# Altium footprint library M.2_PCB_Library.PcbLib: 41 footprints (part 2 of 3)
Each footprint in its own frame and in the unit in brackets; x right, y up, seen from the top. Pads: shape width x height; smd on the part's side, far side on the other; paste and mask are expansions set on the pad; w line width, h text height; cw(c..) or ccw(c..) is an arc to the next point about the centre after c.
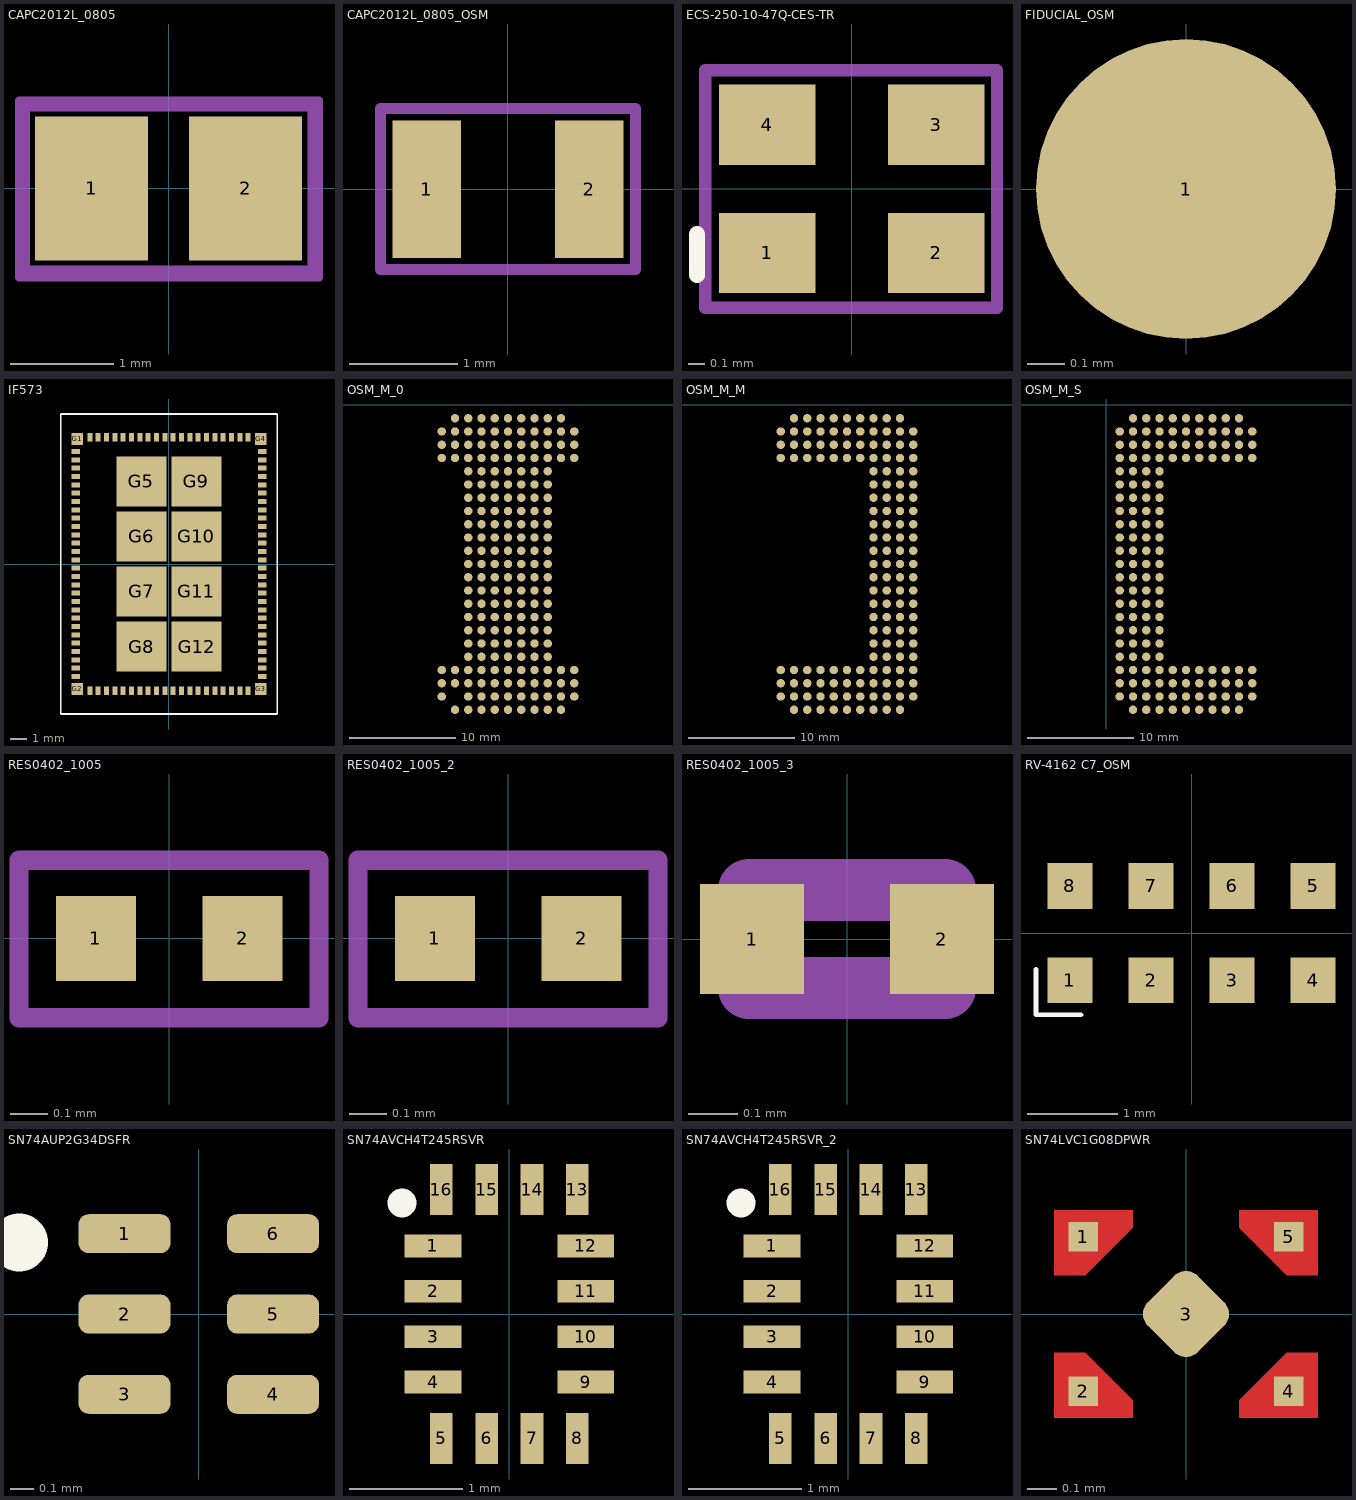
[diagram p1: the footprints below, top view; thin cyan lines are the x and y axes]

## CAPC2012L_0805 [mm] "Chip Capacitor, Body 2.0x1.3mm, IPC High Density"
height 1.1
pads (2):
  rect 1.1x1.4 smd paste-0.12 mask+0.06: 1(-0.75,0) 2(0.75,0)
Mechanical 9:
  lines w0.076: -1.455,-0.866 1.463,-0.866 1.463,0.853 -1.455,0.853 -1.455,-0.866
Top Assembly:
  lines w0.102: -1.4,-0.8 -1.4,0.8 1.4,0.8 1.4,-0.8 -1.4,-0.8
  text "'.Designator'" at -1.311,-0.305 h1.02
3D body "CAP0805.stp": height 0.78, standoff 0, extent -1,-0.625 1,0.625

## CAPC2012L_0805_OSM [mm] "Chip Capacitor, Body 2.0x1.3mm, IPC High Density"
height 1.1
pads (2):
  rect 0.635x1.27 smd paste-0.12 mask+0.06: 1(-0.75,0) 2(0.75,0)
Mechanical 9:
  lines w0.076: -1.165,-0.732 -1.165,0.733 1.166,0.733 1.166,-0.732 -1.165,-0.732
Top Assembly:
  lines w0.102: -1.178,-0.745 1.179,-0.745 1.179,0.746 -1.178,0.746 -1.178,-0.745
  text "'.Designator'" at -1.965,-0.277 h1.02
3D body "CAP0805.stp": height 0.78, standoff 0, extent -1,-0.625 1,0.625

## ECS-250-10-47Q-CES-TR [mm]
height 0.6
pads (4):
  rect 0.6x0.5 smd paste-0.08 mask+0.06: 1(-0.525,-0.398) 2(0.525,-0.398) 3(0.525,0.398) 4(-0.525,0.398)
Top Overlay:
  lines w0.102: -0.962,-0.535 -0.962,-0.281
Mechanical 9:
  lines w0.076: -0.911,-0.738 -0.911,0.737 0.903,0.737 0.903,-0.738 -0.911,-0.738
Top Assembly:
  text "'.Designator'" at -1.717,-0.155 h0.76
3D body "ECS-250-10-47Q-CES-TR.stp": height 0.45, standoff 0, extent -0.835,-0.635 0.835,0.635

## FIDUCIAL_OSM [mm]
pads (1):
  round 0.8 smd paste+0 mask+0: 1(0,0)
Mechanical 1:

## IF573 [mm] "BD1249, 0ZCA0110FF2E,"
height 0.8
pads (108):
  rect 0.5x0.3 smd mask+0.051: 1(-5.594,6.76) 2(-5.594,6.26) 3(-5.594,5.76) 4(-5.594,5.26) 5(-5.594,4.76) 6(-5.594,4.26) 7(-5.594,3.76) 8(-5.594,3.26) 9(-5.594,2.76) 10(-5.594,2.26) 11(-5.594,1.76) 12(-5.594,1.26) 13(-5.594,0.76) 14(-5.594,0.26) 15(-5.594,-0.24) 16(-5.594,-0.74) 17(-5.594,-1.24) 18(-5.594,-1.74) 19(-5.594,-2.24) 20(-5.594,-2.74) 21(-5.594,-3.24) 22(-5.594,-3.74) 23(-5.594,-4.24) 24(-5.594,-4.74) 25(-5.594,-5.24) 26(-5.594,-5.74) 27(-5.594,-6.24) 28(-5.594,-6.74) 49(5.606,-6.74) 50(5.606,-6.24) 51(5.606,-5.74) 52(5.606,-5.24) 53(5.606,-4.74) 54(5.606,-4.24) 55(5.606,-3.74) 56(5.606,-3.24) 57(5.606,-2.74) 58(5.606,-2.24) 59(5.606,-1.74) 60(5.606,-1.24) 61(5.606,-0.74) 62(5.606,-0.24) 63(5.606,0.26) 64(5.606,0.76) 65(5.606,1.26) 66(5.606,1.76) 67(5.606,2.26) 68(5.606,2.76) 69(5.606,3.26) 70(5.606,3.76) 71(5.606,4.26) 72(5.606,4.76) 73(5.606,5.26) 74(5.606,5.76) 75(5.606,6.26) 76(5.606,6.76)
  rect 0.3x0.5 smd mask+0.051: 29(-4.744,-7.59) 30(-4.244,-7.59) 31(-3.744,-7.59) 32(-3.244,-7.59) 33(-2.744,-7.59) 34(-2.244,-7.59) 35(-1.744,-7.59) 36(-1.244,-7.59) 37(-0.744,-7.59) 38(-0.244,-7.59) 39(0.256,-7.59) 40(0.756,-7.59) 41(1.256,-7.59) 42(1.756,-7.59) 43(2.256,-7.59) 44(2.756,-7.59) 45(3.256,-7.59) 46(3.756,-7.59) 47(4.256,-7.59) 48(4.756,-7.59) 77(4.756,7.61) 78(4.256,7.61) 79(3.756,7.61) 80(3.256,7.61) 81(2.756,7.61) 82(2.256,7.61) 83(1.756,7.61) 84(1.256,7.61) 85(0.756,7.61) 86(0.256,7.61) 87(-0.244,7.61) 88(-0.744,7.61) 89(-1.244,7.61) 90(-1.744,7.61) 91(-2.244,7.61) 92(-2.744,7.61) 93(-3.244,7.61) 94(-3.744,7.61) 95(-4.244,7.61) 96(-4.744,7.61)
  rect 0.7x0.7 smd mask+0.051: G1(-5.494,7.51) G2(-5.494,-7.49) G3(5.506,-7.49) G4(5.506,7.51)
  rect 3x3 smd mask+0.051: G5(-1.644,4.96) G6(-1.644,1.66) G7(-1.644,-1.64) G8(-1.644,-4.94) G9(1.656,4.96) G10(1.656,1.66) G11(1.656,-1.64) G12(1.656,-4.94)
Top Overlay:
  lines w0.102: -6.494,-8.99 -6.494,9.01 6.506,9.01 6.506,-8.99 -6.494,-8.99
3D body "453-00117-R1.0.STEP": height 1.94, standoff 0.01, extent -6.494,-8.99 6.506,9.01

## OSM_M_0 [mm]
height 1.5
pads (188):
  round 0.8 smd: A14(17.5,-28.75) A15(18.75,-28.75) A16(20,-28.75) A17(21.25,-28.75) A18(22.5,-28.75) A19(23.75,-28.75) A20(25,-28.75) A21(26.25,-28.75) A22(27.5,-28.75) AA13(16.25,-3.75) AA14(17.5,-3.75) AA15(18.75,-3.75) AA16(20,-3.75) AA17(21.25,-3.75) AA18(22.5,-3.75) AA19(23.75,-3.75) AA20(25,-3.75) AA21(26.25,-3.75) AA22(27.5,-3.75) AA23(28.75,-3.75) AB13(16.25,-2.5) AB14(17.5,-2.5) AB15(18.75,-2.5) AB16(20,-2.5) AB17(21.25,-2.5) AB18(22.5,-2.5) AB19(23.75,-2.5) AB20(25,-2.5) AB21(26.25,-2.5) AB22(27.5,-2.5) AB23(28.75,-2.5) AC14(17.5,-1.25) AC15(18.75,-1.25) AC16(20,-1.25) AC17(21.25,-1.25) AC18(22.5,-1.25) AC19(23.75,-1.25) AC20(25,-1.25) AC21(26.25,-1.25) AC22(27.5,-1.25) B13(16.25,-27.5) B15(18.75,-27.5) B16(20,-27.5) B17(21.25,-27.5) B18(22.5,-27.5) B19(23.75,-27.5) B20(25,-27.5) B21(26.25,-27.5) B22(27.5,-27.5) B23(28.75,-27.5) C13(16.25,-26.25) C14(17.5,-26.25) C15(18.75,-26.25) C16(20,-26.25) C17(21.25,-26.25) C18(22.5,-26.25) C19(23.75,-26.25) C20(25,-26.25) C21(26.25,-26.25) C22(27.5,-26.25) C23(28.75,-26.25) D13(16.25,-25) D14(17.5,-25) D15(18.75,-25) D16(20,-25) D17(21.25,-25) D18(22.5,-25) D19(23.75,-25) D20(25,-25) D21(26.25,-25) D22(27.5,-25) D23(28.75,-25) E15(18.75,-23.75) E16(20,-23.75) E17(21.25,-23.75) E18(22.5,-23.75) E19(23.75,-23.75) E20(25,-23.75) E21(26.25,-23.75) F15(18.75,-22.5) F16(20,-22.5) F17(21.25,-22.5) F18(22.5,-22.5) F19(23.75,-22.5) F20(25,-22.5) F21(26.25,-22.5) G15(18.75,-21.25) G16(20,-21.25) G17(21.25,-21.25) G18(22.5,-21.25) G19(23.75,-21.25) G20(25,-21.25) G21(26.25,-21.25) H15(18.75,-20) H16(20,-20) H17(21.25,-20) H18(22.5,-20) H19(23.75,-20) H20(25,-20) H21(26.25,-20) J15(18.75,-18.75) J16(20,-18.75) J17(21.25,-18.75) J18(22.5,-18.75) J19(23.75,-18.75) J20(25,-18.75) J21(26.25,-18.75) K15(18.75,-17.5) K16(20,-17.5) K17(21.25,-17.5) K18(22.5,-17.5) K19(23.75,-17.5) K20(25,-17.5) K21(26.25,-17.5) L15(18.75,-16.25) L16(20,-16.25) L17(21.25,-16.25) L18(22.5,-16.25) L19(23.75,-16.25) L20(25,-16.25) L21(26.25,-16.25) M15(18.75,-15) M16(20,-15) M17(21.25,-15) M18(22.5,-15) M19(23.75,-15) M20(25,-15) M21(26.25,-15) N15(18.75,-13.75) N16(20,-13.75) N17(21.25,-13.75) N18(22.5,-13.75) N19(23.75,-13.75) N20(25,-13.75) N21(26.25,-13.75) P15(18.75,-12.5) P16(20,-12.5) P17(21.25,-12.5) P18(22.5,-12.5) P19(23.75,-12.5) P20(25,-12.5) P21(26.25,-12.5) R15(18.75,-11.25) R16(20,-11.25) R17(21.25,-11.25) R18(22.5,-11.25) R19(23.75,-11.25) R20(25,-11.25) R21(26.25,-11.25) T15(18.75,-10) T16(20,-10) T17(21.25,-10) T18(22.5,-10) T19(23.75,-10) T20(25,-10) T21(26.25,-10) U15(18.75,-8.75) U16(20,-8.75) U17(21.25,-8.75) U18(22.5,-8.75) U19(23.75,-8.75) U20(25,-8.75) U21(26.25,-8.75) V15(18.75,-7.5) V16(20,-7.5) V17(21.25,-7.5) V18(22.5,-7.5) V19(23.75,-7.5) V20(25,-7.5) V21(26.25,-7.5) W15(18.75,-6.25) W16(20,-6.25) W17(21.25,-6.25) W18(22.5,-6.25) W19(23.75,-6.25) W20(25,-6.25) W21(26.25,-6.25) Y13(16.25,-5) Y14(17.5,-5) Y15(18.75,-5) Y16(20,-5) Y17(21.25,-5) Y18(22.5,-5) Y19(23.75,-5) Y20(25,-5) Y21(26.25,-5) Y22(27.5,-5) Y23(28.75,-5)

## OSM_M_M [mm]
height 1.5
pads (144):
  round 0.8 smd: A26(32.5,-28.75) A27(33.75,-28.75) A28(35,-28.75) A29(36.25,-28.75) A30(37.5,-28.75) A31(38.75,-28.75) A32(40,-28.75) A33(41.25,-28.75) A34(42.5,-28.75) AA25(31.25,-3.75) AA26(32.5,-3.75) AA27(33.75,-3.75) AA28(35,-3.75) AA29(36.25,-3.75) AA30(37.5,-3.75) AA31(38.75,-3.75) AA32(40,-3.75) AA33(41.25,-3.75) AA34(42.5,-3.75) AA35(43.75,-3.75) AB25(31.25,-2.5) AB26(32.5,-2.5) AB27(33.75,-2.5) AB28(35,-2.5) AB29(36.25,-2.5) AB30(37.5,-2.5) AB31(38.75,-2.5) AB32(40,-2.5) AB33(41.25,-2.5) AB34(42.5,-2.5) AB35(43.75,-2.5) AC26(32.5,-1.25) AC27(33.75,-1.25) AC28(35,-1.25) AC29(36.25,-1.25) AC30(37.5,-1.25) AC31(38.75,-1.25) AC32(40,-1.25) AC33(41.25,-1.25) AC34(42.5,-1.25) B25(31.25,-27.5) B26(32.5,-27.5) B27(33.75,-27.5) B28(35,-27.5) B29(36.25,-27.5) B30(37.5,-27.5) B31(38.75,-27.5) B32(40,-27.5) B33(41.25,-27.5) B34(42.5,-27.5) B35(43.75,-27.5) C25(31.25,-26.25) C26(32.5,-26.25) C27(33.75,-26.25) C28(35,-26.25) C29(36.25,-26.25) C30(37.5,-26.25) C31(38.75,-26.25) C32(40,-26.25) C33(41.25,-26.25) C34(42.5,-26.25) C35(43.75,-26.25) D25(31.25,-25) D26(32.5,-25) D27(33.75,-25) D28(35,-25) D29(36.25,-25) D30(37.5,-25) D31(38.75,-25) D32(40,-25) D33(41.25,-25) D34(42.5,-25) D35(43.75,-25) E32(40,-23.75) E33(41.25,-23.75) E34(42.5,-23.75) E35(43.75,-23.75) F32(40,-22.5) F33(41.25,-22.5) F34(42.5,-22.5) F35(43.75,-22.5) G32(40,-21.25) G33(41.25,-21.25) G34(42.5,-21.25) G35(43.75,-21.25) H32(40,-20) H33(41.25,-20) H34(42.5,-20) H35(43.75,-20) J32(40,-18.75) J33(41.25,-18.75) J34(42.5,-18.75) J35(43.75,-18.75) K32(40,-17.5) K33(41.25,-17.5) K34(42.5,-17.5) K35(43.75,-17.5) L32(40,-16.25) L33(41.25,-16.25) L34(42.5,-16.25) L35(43.75,-16.25) M32(40,-15) M33(41.25,-15) M34(42.5,-15) M35(43.75,-15) N32(40,-13.75) N33(41.25,-13.75) N34(42.5,-13.75) N35(43.75,-13.75) P32(40,-12.5) P33(41.25,-12.5) P34(42.5,-12.5) P35(43.75,-12.5) R32(40,-11.25) R33(41.25,-11.25) R34(42.5,-11.25) R35(43.75,-11.25) T32(40,-10) T33(41.25,-10) T34(42.5,-10) T35(43.75,-10) U32(40,-8.75) U33(41.25,-8.75) U34(42.5,-8.75) U35(43.75,-8.75) V32(40,-7.5) V33(41.25,-7.5) V34(42.5,-7.5) V35(43.75,-7.5) W32(40,-6.25) W33(41.25,-6.25) W34(42.5,-6.25) W35(43.75,-6.25) Y25(31.25,-5) Y26(32.5,-5) Y27(33.75,-5) Y28(35,-5) Y29(36.25,-5) Y30(37.5,-5) Y31(38.75,-5) Y32(40,-5) Y33(41.25,-5) Y34(42.5,-5) Y35(43.75,-5)

## OSM_M_S [mm]
height 1.5
pads (144):
  round 0.8 smd: A2(2.5,-28.75) A3(3.75,-28.75) A4(5,-28.75) A5(6.25,-28.75) A6(7.5,-28.75) A7(8.75,-28.75) A8(10,-28.75) A9(11.25,-28.75) A10(12.5,-28.75) AA1(1.25,-3.75) AA2(2.5,-3.75) AA3(3.75,-3.75) AA4(5,-3.75) AA5(6.25,-3.75) AA6(7.5,-3.75) AA7(8.75,-3.75) AA8(10,-3.75) AA9(11.25,-3.75) AA10(12.5,-3.75) AA11(13.75,-3.75) AB1(1.25,-2.5) AB2(2.5,-2.5) AB3(3.75,-2.5) AB4(5,-2.5) AB5(6.25,-2.5) AB6(7.5,-2.5) AB7(8.75,-2.5) AB8(10,-2.5) AB9(11.25,-2.5) AB10(12.5,-2.5) AB11(13.75,-2.5) AC2(2.5,-1.25) AC3(3.75,-1.25) AC4(5,-1.25) AC5(6.25,-1.25) AC6(7.5,-1.25) AC7(8.75,-1.25) AC8(10,-1.25) AC9(11.25,-1.25) AC10(12.5,-1.25) B1(1.25,-27.5) B2(2.5,-27.5) B3(3.75,-27.5) B4(5,-27.5) B5(6.25,-27.5) B6(7.5,-27.5) B7(8.75,-27.5) B8(10,-27.5) B9(11.25,-27.5) B10(12.5,-27.5) B11(13.75,-27.5) C1(1.25,-26.25) C2(2.5,-26.25) C3(3.75,-26.25) C4(5,-26.25) C5(6.25,-26.25) C6(7.5,-26.25) C7(8.75,-26.25) C8(10,-26.25) C9(11.25,-26.25) C10(12.5,-26.25) C11(13.75,-26.25) D1(1.25,-25) D2(2.5,-25) D3(3.75,-25) D4(5,-25) D5(6.25,-25) D6(7.5,-25) D7(8.75,-25) D8(10,-25) D9(11.25,-25) D10(12.5,-25) D11(13.75,-25) E1(1.25,-23.75) E2(2.5,-23.75) E3(3.75,-23.75) E4(5,-23.75) F1(1.25,-22.5) F2(2.5,-22.5) F3(3.75,-22.5) F4(5,-22.5) G1(1.25,-21.25) G2(2.5,-21.25) G3(3.75,-21.25) G4(5,-21.25) H1(1.25,-20) H2(2.5,-20) H3(3.75,-20) H4(5,-20) J1(1.25,-18.75) J2(2.5,-18.75) J3(3.75,-18.75) J4(5,-18.75) K1(1.25,-17.5) K2(2.5,-17.5) K3(3.75,-17.5) K4(5,-17.5) L1(1.25,-16.25) L2(2.5,-16.25) L3(3.75,-16.25) L4(5,-16.25) M1(1.25,-15) M2(2.5,-15) M3(3.75,-15) M4(5,-15) N1(1.25,-13.75) N2(2.5,-13.75) N3(3.75,-13.75) N4(5,-13.75) P1(1.25,-12.5) P2(2.5,-12.5) P3(3.75,-12.5) P4(5,-12.5) R1(1.25,-11.25) R2(2.5,-11.25) R3(3.75,-11.25) R4(5,-11.25) T1(1.25,-10) T2(2.5,-10) T3(3.75,-10) T4(5,-10) U1(1.25,-8.75) U2(2.5,-8.75) U3(3.75,-8.75) U4(5,-8.75) V1(1.25,-7.5) V2(2.5,-7.5) V3(3.75,-7.5) V4(5,-7.5) W1(1.25,-6.25) W2(2.5,-6.25) W3(3.75,-6.25) W4(5,-6.25) Y1(1.25,-5) Y2(2.5,-5) Y3(3.75,-5) Y4(5,-5) Y5(6.25,-5) Y6(7.5,-5) Y7(8.75,-5) Y8(10,-5) Y9(11.25,-5) Y10(12.5,-5) Y11(13.75,-5)

## RES0402_1005 [mm]
pads (2):
  rect 0.212x0.225 smd: 1(-0.194,0) 2(0.194,0)
Top Courtyard:
  lines w0.051: -0.398,-0.21 0.396,-0.21 0.396,0.207 -0.398,0.207 -0.398,-0.21
3D body "01005_PAN.step": height 0.15, standoff 0, extent -0.216,-0.114 0.216,0.114

## RES0402_1005_2 [mm]
pads (2):
  rect 0.212x0.225 smd: 1(-0.194,0) 2(0.194,0)
Top Courtyard:
  lines w0.051: -0.398,-0.21 0.396,-0.21 0.396,0.207 -0.398,0.207 -0.398,-0.21
3D body "01005_PAN.step": height 0.15, standoff 0, extent -0.216,-0.114 0.216,0.114

## RES0402_1005_3 [mm]
pads (2):
  rect 0.212x0.225 smd: 1(-0.194,0) 2(0.194,0)
Top Courtyard:
  lines w0.127: -0.2,-0.1 0.2,-0.1 0.2,0.1 -0.2,0.1 -0.2,-0.1
3D body "01005_PAN.step": height 0.15, standoff 0, extent -0.216,-0.114 0.216,0.114

## RV-4162 C7_OSM [mm]
pads (8):
  rect 0.5x0.508 smd: 1(-1.35,-0.524) 2(-0.45,-0.524) 3(0.45,-0.524) 4(1.35,-0.524) 5(1.35,0.524) 6(0.45,0.524) 7(-0.45,0.524) 8(-1.35,0.524)
Top Overlay:
  lines w0.051: -1.727,-0.4 -1.727,-0.908 -1.227,-0.908
3D body "RV-3028-C7-32.768KHZ-1PPM-TA-QC.STEP": height 0.8, standoff 0, extent -1.6,-0.75 1.6,0.75

## SN74AUP2G34DSFR [mm]
height 0.8
pads (6):
  rrect50% 0.4x0.17 smd: 1(-0.324,0.35) 2(-0.324,0) 3(-0.324,-0.35) 4(0.324,-0.35) 5(0.324,0) 6(0.324,0.35)
Top Overlay:
  lines w0.254: -0.784,0.311 -0.784,0.312
3D body "SN74AUP2G34DSFR.step": height 0.4, standoff 0, extent -0.5,-0.5 0.5,0.5

## SN74AVCH4T245RSVR [mm]
height 0.8
pads (16):
  rect 0.5x0.2 smd: 1(-0.674,0.6) 2(-0.673,0.2) 3(-0.673,-0.2) 4(-0.673,-0.6) 9(0.673,-0.6) 10(0.673,-0.2) 11(0.673,0.2) 12(0.673,0.6)
  rect 0.2x0.45 smd: 5(-0.6,-1.098) 6(-0.2,-1.098) 7(0.2,-1.098) 8(0.6,-1.098) 13(0.6,1.098) 14(0.2,1.098) 15(-0.2,1.098) 16(-0.6,1.098)
Top Overlay:
  lines w0.254: -0.947,0.98 -0.946,0.981
3D body "SN74AVCH4T245RSVR.step": height 0.55, standoff 0, extent -0.9,-1.3 0.9,1.3

## SN74AVCH4T245RSVR_2 [mm]
pads (16):
  rect 0.5x0.2 smd: 1(-0.674,0.6) 2(-0.673,0.2) 3(-0.673,-0.2) 4(-0.673,-0.6) 9(0.673,-0.6) 10(0.673,-0.2) 11(0.673,0.2) 12(0.673,0.6)
  rect 0.2x0.45 smd: 5(-0.6,-1.098) 6(-0.2,-1.098) 7(0.2,-1.098) 8(0.6,-1.098) 13(0.6,1.098) 14(0.2,1.098) 15(-0.2,1.098) 16(-0.6,1.098)
Top Overlay:
  lines w0.254: -0.947,0.98 -0.946,0.981
3D body "SN74AVCH4T245RSVR.step": height 0.55, standoff 0, extent -0.9,-1.3 0.9,1.3

## SN74LVC1G08DPWR [mm]
height 0.8
pads (5):
  rect 0.1x0.1 smd mask+0: 1(-0.346,0.261) 2(-0.346,-0.261) 4(0.346,-0.261) 5(0.346,0.261)
  rrect50% 0.24x0.24 smd rot 135: 3(0,0)
Top Layer:
  region: 0.444,0.13 0.444,0.35 0.18,0.35 0.18,0.29 0.34,0.13
  region: 0.444,-0.13 0.444,-0.35 0.18,-0.35 0.18,-0.29 0.34,-0.13
  region: -0.444,0.13 -0.444,0.35 -0.18,0.35 -0.18,0.29 -0.34,0.13
  region: -0.444,-0.13 -0.444,-0.35 -0.18,-0.35 -0.18,-0.29 -0.34,-0.13
Top Paste:
  region: -0.444,-0.13 -0.444,-0.35 -0.18,-0.35 -0.18,-0.29 -0.34,-0.13
  region: 0.444,0.13 0.444,0.35 0.18,0.35 0.18,0.29 0.34,0.13
  region: 0.444,-0.13 0.444,-0.35 0.18,-0.35 0.18,-0.29 0.34,-0.13
  region: -0.444,0.13 -0.444,0.35 -0.18,0.35 -0.18,0.29 -0.34,0.13
Top Solder:
  region: -0.506,0.076 -0.303,0.076 -0.126,0.253 -0.126,0.406 -0.506,0.406
  region: 0.506,-0.076 0.303,-0.076 0.126,-0.253 0.126,-0.406 0.506,-0.406
  region: 0.506,0.076 0.303,0.076 0.126,0.253 0.126,0.406 0.506,0.406
  region: -0.506,-0.076 -0.303,-0.076 -0.126,-0.253 -0.126,-0.406 -0.506,-0.406
3D body "SN74LVC1G08DPWR.step": height 0.4, standoff 0, extent -0.4,-0.4 0.4,0.4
